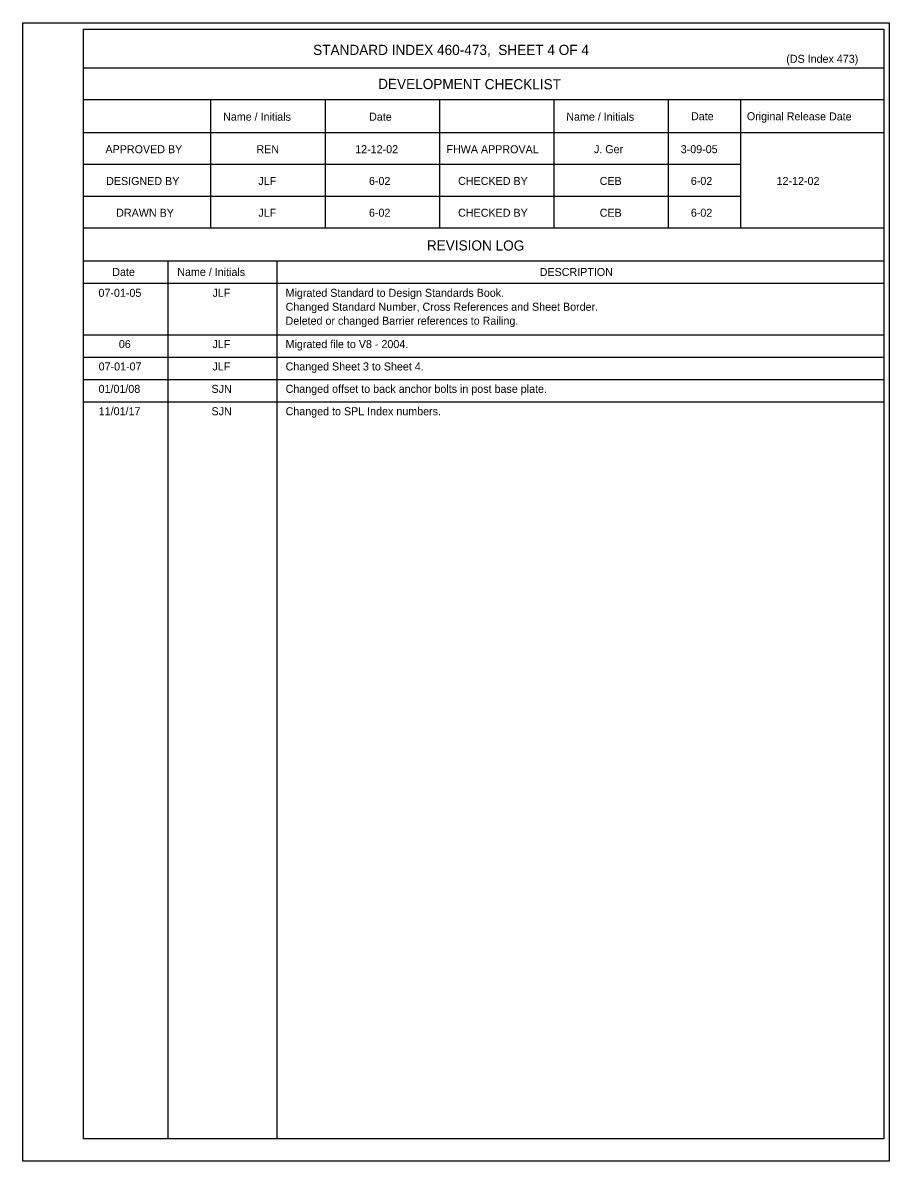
# Model space of a CAD drawing. Extents: x 21587 to 21656.3, y 56117.4 to 56157.3.
# Drawn here: x 21634.51 to 21656.33, y 56124.78 to 56153.45 of the extents above; entities that cross this region are included whole.
import ezdxf

# ---------------------------------------------------------------- set-up
doc = ezdxf.new("R2010")
doc.units = 0
for name, color, linetype in [('Border', 7, 'Continuous'), ('PlotBorder_dp', 7, 'Continuous'), ('SheetBorder_dp', 7, 'Continuous')]:
    doc.layers.add(name, color=color, linetype=linetype)

msp = doc.modelspace()

# ---------------------------------------------------------------- linework, layer by layer
at = {"layer": 'Border'}
for p, q in [((21656.191, 56152.307), (21636.044, 56152.307)), ((21656.191, 56151.507), (21636.044, 56151.507)), ((21639.244, 56151.507), (21639.244, 56148.279)), ((21642.124, 56151.507), (21642.124, 56148.279)), ((21645.004, 56151.507), (21645.004, 56148.279)), ((21647.884, 56151.507), (21647.884, 56148.279)), ((21650.764, 56151.507), (21650.764, 56148.279)), ((21652.579, 56151.507), (21652.579, 56148.279)), ((21656.191, 56150.679), (21636.044, 56150.679)), ((21652.579, 56149.879), (21636.044, 56149.879)), ((21652.579, 56149.079), (21636.044, 56149.079)), ((21656.191, 56148.279), (21636.044, 56148.279)), ((21656.191, 56147.451), (21636.044, 56147.451)), ((21638.165, 56147.451), (21638.165, 56125.345)), ((21640.907, 56147.451), (21640.907, 56125.345)), ((21656.191, 56146.887), (21636.044, 56146.887))]:
    msp.add_line(p, q, dxfattribs=at)
msp.add_lwpolyline([(21636.045, 56153.287), (21656.191, 56153.287), (21656.191, 56125.345), (21636.045, 56125.345)], close=True, dxfattribs=at)
at = {"layer": 'PlotBorder_dp'}
for p, q in [((21636.045, 56145.596), (21656.191, 56145.596)), ((21636.045, 56145.033), (21656.191, 56145.033)), ((21636.045, 56144.469), (21656.191, 56144.469)), ((21636.045, 56143.905), (21656.191, 56143.905)), ((21634.514, 56124.783), (21634.514, 56124.783))]:
    msp.add_line(p, q, dxfattribs=at)
msp.add_lwpolyline([(21634.514, 56153.45), (21656.327, 56153.45), (21656.327, 56124.783), (21634.514, 56124.783)], close=True, dxfattribs=at)

# ---------------------------------------------------------------- texts
at = {"layer": 'SheetBorder_dp'}
for s, height, p in [('STANDARD INDEX 460-473,  SHEET 4 OF 4', 0.256, (21641.824, 56152.639)), ('(DS Index 473)', 0.2016, (21653.735, 56152.442)), ('REN', 0.2016, (21640.396, 56150.166)), ('12-12-02', 0.2016, (21642.883, 56150.166)), ('J. Ger', 0.2016, (21648.894, 56150.166)), ('3-09-05', 0.2016, (21651.078, 56150.166)), ('JLF', 0.2016, (21640.444, 56149.366)), ('6-02', 0.2016, (21643.229, 56149.366)), ('CEB', 0.2016, (21649.039, 56149.366)), ('6-02', 0.2016, (21651.333, 56149.366)), ('12-12-02', 0.2016, (21653.492, 56149.366)), ('JLF', 0.2016, (21640.444, 56148.566)), ('6-02', 0.2016, (21643.229, 56148.566)), ('CEB', 0.2016, (21649.039, 56148.566)), ('6-02', 0.2016, (21651.333, 56148.566)), ('DESCRIPTION', 0.2016, (21647.528, 56147.074)), ('07-01-05', 0.2016, (21636.42, 56146.549)), ('JLF', 0.2016, (21639.291, 56146.549)), ('Migrated Standard to Design Standards Book.', 0.2016, (21641.131, 56146.549)), ('Changed Standard Number, Cross References and Sheet Border.', 0.2016, (21641.131, 56146.198)), ('Deleted or changed Barrier references to Railing.', 0.2016, (21641.131, 56145.846)), ('06', 0.2016, (21636.932, 56145.258)), ('JLF', 0.2016, (21639.291, 56145.258)), ('Migrated file to V8 - 2004.', 0.2016, (21641.131, 56145.258)), ('07-01-07', 0.2016, (21636.424, 56144.695)), ('JLF', 0.2016, (21639.291, 56144.695)), ('Changed Sheet 3 to Sheet 4.', 0.2016, (21641.131, 56144.695)), ('01/01/08', 0.2016, (21636.422, 56144.131)), ('SJN', 0.2016, (21639.266, 56144.131)), ('Changed offset to back anchor bolts in post base plate.', 0.2016, (21641.131, 56144.131)), ('11/01/17', 0.2016, (21636.426, 56143.567)), ('SJN', 0.2016, (21639.266, 56143.567)), ('Changed to SPL Index numbers.', 0.2016, (21641.131, 56143.567))]:
    msp.add_text(s, height=height, dxfattribs=at).set_placement(p)
for s, height, p in [('DEVELOPMENT CHECKLIST', 0.256, (21643.46, 56151.783)), ('Name / Initials', 0.2016, (21639.557, 56150.986)), ('Date', 0.2016, (21643.232, 56150.984)), ('Name / Initials', 0.2016, (21648.197, 56150.986)), ('Date', 0.2016, (21651.337, 56150.996)), ('Original Release Date', 0.2016, (21652.743, 56150.996)), ('APPROVED BY', 0.2016, (21636.596, 56150.167)), ('FHWA APPROVAL', 0.2016, (21645.18, 56150.167)), ('DESIGNED BY', 0.2016, (21636.613, 56149.366)), ('CHECKED BY', 0.2016, (21645.474, 56149.367)), ('DRAWN BY', 0.2016, (21636.866, 56148.566)), ('CHECKED BY', 0.2016, (21645.474, 56148.567)), ('REVISION LOG', 0.256, (21644.686, 56147.718)), ('Name / Initials', 0.2016, (21638.403, 56147.076)), ('Date', 0.2016, (21636.767, 56147.075))]:
    msp.add_text(s, height=height, rotation=359.8756, dxfattribs=at).set_placement(p)

doc.saveas('drawing.dxf')
